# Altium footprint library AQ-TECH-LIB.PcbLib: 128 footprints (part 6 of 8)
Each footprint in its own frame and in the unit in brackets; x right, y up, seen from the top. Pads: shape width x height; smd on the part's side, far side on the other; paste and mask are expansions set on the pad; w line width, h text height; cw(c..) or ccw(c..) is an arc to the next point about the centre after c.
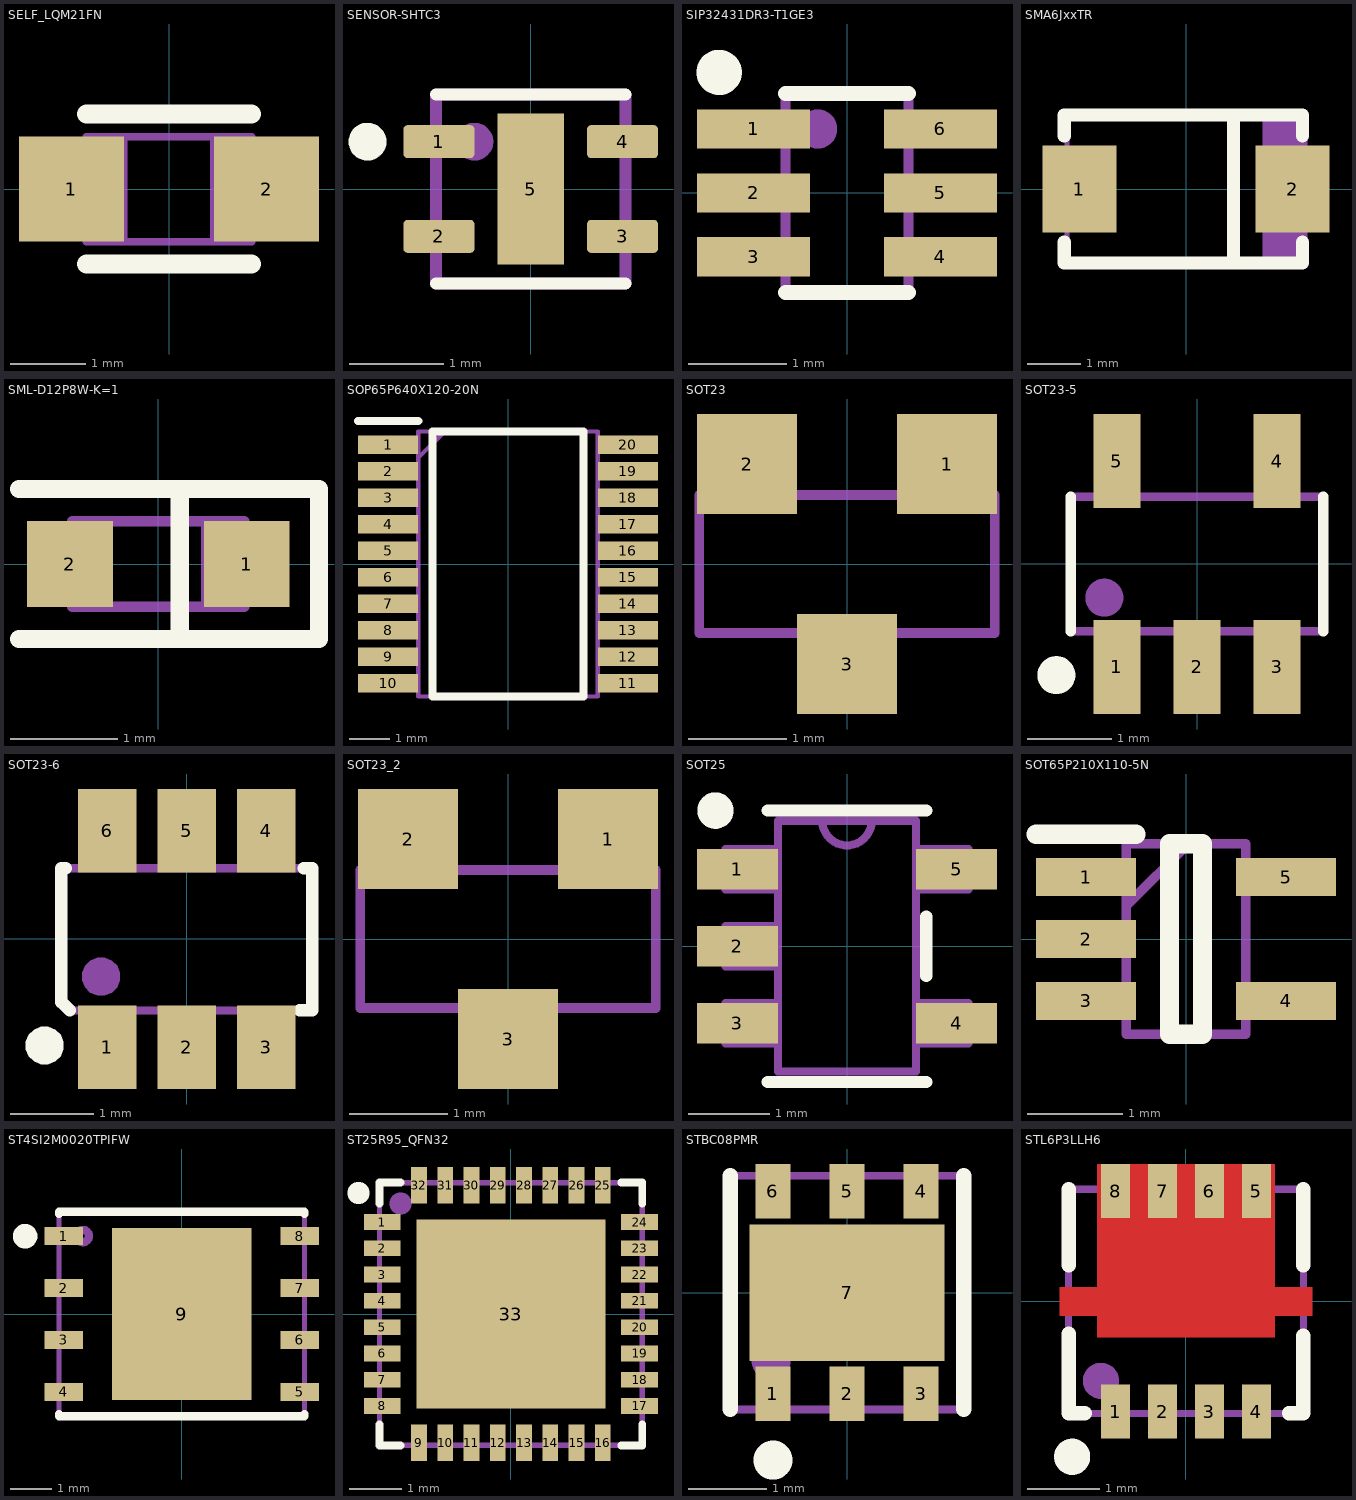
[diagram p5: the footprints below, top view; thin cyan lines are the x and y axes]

## SELF_LQM21FN [mm]
height 1.45
pads (2):
  rect 1.4x1.4 smd paste+0 mask+0.1: 1(-1.3,0) 2(1.3,0)
Top Overlay:
  lines w0.25: -1.1,-1 1.1,-1 ; -1.1,1 1.1,1
Mechanical 3:
  lines w0.1: -1.1,-0.7 -1.1,0.7 ; -1.1,-0.7 -0.6,-0.7 -0.6,0.7 -1.1,0.7 ; -1.1,-0.7 -1.1,0.7 ; -1.1,-0.7 1.1,-0.7 ; -1.1,0.7 1.1,0.7 ; 1.1,-0.7 1.1,0.7 ; 1.1,-0.7 0.6,-0.7 0.6,0.7 1.1,0.7 ; 1.1,-0.7 1.1,0.7
  text ".Designator" at -0.725,-0.125 h0.84
3D body: height 1.45, standoff 0, extent -1.1,-0.7 1.1,0.7

## SENSOR-SHTC3 [mm]
height 0.75
pads (5):
  rrect25% 0.75x0.35 smd mask+0.05: 1(-0.97,0.5) 2(-0.97,-0.5) 3(0.97,-0.5) 4(0.97,0.5)
  rect 0.7x1.6 smd mask+0.05: 5(0,0)
Top Overlay:
  circle w0.2: c-1.725,0.5 r0.1
  lines w0.127: -1,-1 1,-1 ; -1,1 1,1
Mechanical 3:
  circle w0.2: c-0.595,0.5 r0.1
  lines w0.127: -1,-1 -1,1 1,1 1,-1 -1,-1
  text ".Designator" at 0,0 h0.84
3D body "step_temp.STEP": height 0.75, standoff 0, extent -1,-1 1,1

## SIP32431DR3-T1GE3 [mm] "SC70-6"
height 1.1
pads (6):
  rect 1.15x0.4 smd mask+0.05: 1(-0.95,0.65) 2(-0.95,0) 3(-0.95,-0.65) 4(0.95,-0.65) 5(0.95,0) 6(0.95,0.65)
Top Overlay:
  circle w0.3: c-1.3,1.225 r0.08
  lines w0.15: -0.625,-1.012 0.625,-1.012 ; -0.625,1.012 0.625,1.012
Mechanical 3:
  circle w0.2: c-0.3,0.65 r0.1
  lines w0.1: -0.625,-1.012 -0.625,1.012 0.625,1.012 0.625,-1.012 -0.625,-1.012
  text ".Designator" at 0,0 h0.84
3D body "MIC94092YC6_TR.stp": height 1.1, standoff 0, extent -1.05,-1.012 1.05,1.012

## SMA6JxxTR [mm]
height 2.65
pads (2):
  rect 1.4x1.64 smd paste+0 mask+0.1: 1(-2.015,0) 2(2.015,0)
Top Overlay:
  lines w0.25: -2.3,-1 -2.3,-1.4 2.2,-1.4 2.2,-1 ; -2.3,1 -2.3,1.4 2.2,1.4 2.2,1 ; 0.9,-1.3 0.9,1.4
Mechanical 3:
  region: 1.5,-1.39 2.24,-1.39 2.24,1.4 1.5,1.4
  lines w0.1: 1.5,-1.395 1.5,1.395 ; -2.64,-0.735 -2.64,0.735 -2.25,0.735 -2.25,-0.735 -2.64,-0.735 ; -2.25,-1.395 -2.25,1.395 2.25,1.395 2.25,-1.395 -2.25,-1.395 ; 2.25,-0.735 2.64,-0.735 2.64,0.735 2.25,0.735 2.25,-0.735
  text ".Designator" at 0,0 h0.84
3D body "DO214AC(refusion).stp": height 2.4, standoff 0, extent -2.6,-1.3 2.6,1.3

## SML-D12P8W-K=1 [mm] "LED VERTE"
height 0.55
pads (2):
  rect 0.8x0.8 smd: 1(0.825,0) 2(-0.825,0)
Top Overlay:
  lines w0.17: -1.3,-0.7 1.5,-0.7 1.5,0.7 1.05,0.7 -1.3,0.7 ; 0.2,-0.7 0.2,0.7
Mechanical 3:
  rectangle: 0.4,-0.4 0.8,0.4
  lines w0.1: -0.8,-0.4 -0.8,0.4 0.8,0.4 0.8,-0.4 -0.8,-0.4
  text "'.Designator'" at -1.75,-0.65 h0.8
3D body: height 0.55, standoff 0, extent -0.8,-0.4 0.8,0.4

## SOP65P640X120-20N [mm]
pads (20):
  rect 1.475x0.45 smd mask+0.05: 1(-2.938,2.925) 2(-2.938,2.275) 3(-2.938,1.625) 4(-2.938,0.975) 5(-2.938,0.325) 6(-2.938,-0.325) 7(-2.938,-0.975) 8(-2.938,-1.625) 9(-2.938,-2.275) 10(-2.938,-2.925) 11(2.938,-2.925) 12(2.938,-2.275) 13(2.938,-1.625) 14(2.938,-0.975) 15(2.938,-0.325) 16(2.938,0.325) 17(2.938,0.975) 18(2.938,1.625) 19(2.938,2.275) 20(2.938,2.925)
Top Overlay:
  lines w0.2: -3.675,3.5 -2.2,3.5 ; -1.85,-3.25 -1.85,3.25 1.85,3.25 1.85,-3.25 -1.85,-3.25
Mechanical 3:
  lines w0.1: -2.2,2.6 -1.55,3.25 ; -2.2,-3.25 2.2,-3.25 2.2,3.25 -2.2,3.25 -2.2,-3.25
  text "'.Designator'" at -0.025,0 h0.8
3D body "STM32L010F4P6.stp": height 1.2, standoff 0, extent -3.2,-3.25 3.2,3.25

## SOT23 [mil]
height 44.09
pads (3):
  rect 40x40 smd: 1(40,40) 2(-40,40) 3(0,-40)
Mechanical 3:
  lines w3.94: -59.1,-27.6 -59.1,27.6 -47,27.6 -47,49.2 -28,49.2 -28,27.6 28,27.6 28,49.2 47,49.2 47,27.6 59.1,27.6 59.1,-27.6 9.5,-27.6 9.5,-49.2 -9.5,-49.2 -9.5,-27.6 -59.1,-27.6
  text ".Designator" at -28,-21.65 h33.07
3D body "Conception1.stp": height 43.31, standoff 0, extent -59.05,-49.21 59.06,49.22

## SOT23-5 [mil] "refusion"
height 57.09
pads (5):
  rect 22x44 smd paste+0 mask+3.94: 1(-37.4,-48.11) 2(0,-48.11) 3(37.4,-48.11) 4(37.4,48.11) 5(-37.4,48.11)
Top Overlay:
  lines w4.92: -59.06,-31.5 -59.06,31.5 ; 59.06,-31.5 59.06,31.5
  lines w9.84: -65.75,-55.91 cw(c-65.75,-51.97) -65.75,-48.03 cw(c-65.75,-51.97) -65.75,-55.91
Mechanical 3:
  lines w3.94: -59.06,-31.5 59.06,-31.5 59.06,31.5 -59.06,31.5 -59.06,-31.5
  lines w9.84: -43.31,-19.68 ccw(c-43.31,-15.75) -43.31,-11.81 ccw(c-43.31,-15.75) -43.31,-19.68
  text ".Designator" at -54.08,-9.65 h33.07
3D body "sot23-5.stp": height 43.31, standoff 0, extent -59.05,-49.2 59.06,49.22

## SOT23-6 [mm] "refusion"
height 1.4
pads (6):
  rect 0.7x1 smd paste+0 mask+0.05: 1(-0.95,-1.295) 2(0,-1.295) 3(0.95,-1.295) 4(0.95,1.295) 5(0,1.295) 6(-0.95,1.295)
Top Overlay:
  region: -1.7,-1.5 -1.745,-1.5 -1.827,-1.466 -1.891,-1.402 -1.925,-1.32 -1.925,-1.23 -1.891,-1.148 -1.827,-1.084 -1.745,-1.05 -1.7,-1.05 -1.655,-1.05 -1.573,-1.084 -1.509,-1.148 -1.475,-1.23 -1.475,-1.32 -1.509,-1.402 -1.573,-1.466 -1.655,-1.5
  lines w0.15: -1.45,0.845 -1.5,0.845 -1.5,-0.755 -1.4,-0.855 ; 1.35,-0.855 1.5,-0.855 1.5,0.845 1.4,0.845
Mechanical 3:
  region: -1.025,-0.675 -1.07,-0.675 -1.152,-0.641 -1.216,-0.577 -1.25,-0.495 -1.25,-0.405 -1.216,-0.323 -1.152,-0.259 -1.07,-0.225 -1.025,-0.225 -0.98,-0.225 -0.898,-0.259 -0.834,-0.323 -0.8,-0.405 -0.8,-0.495 -0.834,-0.577 -0.898,-0.641 -0.98,-0.675
  lines w0.1: -1.5,-0.755 -1.5,0.845 1.5,0.845 1.5,-0.855 -1.4,-0.855 -1.5,-0.755
  text ".Designator" at 0,0 h1
3D body "SOT23-6(refusion).stp": height 1.45, standoff 0, extent -1.5,-1.5 1.5,1.5

## SOT23_2 [mil]
pads (3):
  rect 40x40 smd: 1(40,40) 2(-40,40) 3(0,-40)
Mechanical 3:
  lines w3.94: -59.1,-27.6 -9.5,-27.6 -9.5,-49.2 9.5,-49.2 9.5,-27.6 59.1,-27.6 59.1,27.6 47,27.6 47,49.2 28,49.2 28,27.6 -28,27.6 -28,49.2 -47,49.2 -47,27.6 -59.1,27.6 -59.1,-27.6
  text ".Designator" at -28,-21.65 h33.07
3D body "Conception1.stp": height 43.31, standoff 0, extent -59.05,-49.21 59.06,49.22

## SOT25 [mm]
height 1.4
pads (5):
  rect 1x0.5 smd: 1(-1.353,0.95) 2(-1.353,0) 3(-1.353,-0.95) 4(1.353,-0.95) 5(1.353,0.95)
Top Overlay:
  circle w0.25: c-1.625,1.675 r0.1
  lines w0.152: -0.977,-1.677 0.977,-1.677 ; -0.977,1.677 0.977,1.677 ; 0.977,-0.367 0.977,0.367
Mechanical 3:
  lines w0.1: -0.305,1.55 ccw(c0,1.55) 0.305,1.55 ; -1.5,-1.2 -0.85,-1.2 -0.85,-0.7 -1.5,-0.7 -1.5,-1.2 ; -1.5,-0.25 -0.85,-0.25 -0.85,0.25 -1.5,0.25 -1.5,-0.25 ; -1.5,0.7 -0.85,0.7 -0.85,1.2 -1.5,1.2 -1.5,0.7 ; -0.85,-1.55 -0.85,1.55 0.85,1.55 0.85,-1.55 -0.85,-1.55 ; 0.85,-1.2 1.5,-1.2 1.5,-0.7 0.85,-0.7 0.85,-1.2 ; 0.85,0.7 1.5,0.7 1.5,1.2 0.85,1.2 0.85,0.7
  text ".Designator" at 0.4,-1.125 h0.84
3D body "SOT25_DIO.step": height 1.45, standoff 0, extent -1.5,-1.55 1.5,1.55

## SOT65P210X110-5N [mm]
pads (5):
  rect 1.05x0.4 smd mask+0.05: 1(-1.05,0.65) 2(-1.05,0) 3(-1.05,-0.65) 4(1.05,-0.65) 5(1.05,0.65)
Top Overlay:
  lines w0.2: -1.575,1.1 -0.525,1.1 ; -0.175,-1 -0.175,1 0.175,1 0.175,-1 -0.175,-1
Mechanical 3:
  lines w0.1: -0.625,0.35 0.025,1 ; -0.625,-1 0.625,-1 0.625,1 -0.625,1 -0.625,-1
  text ".Designator" at 0.245,-1.374 h0.84
3D body "MIC5253-1.8YC5-TR.stp": height 1.1, standoff 0, extent -1.05,-1 1.05,1

## ST4SI2M0020TPIFW [mm]
height 1
pads (9):
  rect 0.94x0.44 smd mask+0.05: 1(-2.885,1.905) 2(-2.885,0.635) 3(-2.885,-0.635) 4(-2.885,-1.905) 5(2.885,-1.905) 6(2.885,-0.635) 7(2.885,0.635) 8(2.885,1.905)
  rect 3.4x4.2 smd paste-3 mask+0.05: 9(0,0)
Top Overlay:
  circle w0.3: c-3.825,1.9 r0.15
  lines w0.2: -3,-2.445 -3,-2.5 3,-2.5 3,-2.445 ; -3,2.445 -3,2.5 3,2.5 3,2.445
Top Paste:
  region: -0.23,0.23 -1.24,0.23 -1.24,1.64 -0.23,1.64
  region: -0.23,-1.64 -1.24,-1.64 -1.24,-0.23 -0.23,-0.23
  region: 1.24,0.23 0.23,0.23 0.23,1.64 1.24,1.64
  region: 1.24,-1.64 0.23,-1.64 0.23,-0.23 1.24,-0.23
Mechanical 3:
  circle w0.2: c-2.415,1.905 r0.15
  lines w0.127: -3,-2.5 -3,2.5 3,2.5 3,-2.5 -3,-2.5
3D body: height 1, standoff 0, extent -3,-2.5 3,2.5
3D body: height 1.01, standoff 0, extent -2.665,1.655 -2.165,2.155

## ST25R95_QFN32 [mm]
height 1
pads (33):
  rect 0.7x0.3 smd mask+0.05: 1(-2.45,1.75) 2(-2.45,1.25) 3(-2.45,0.75) 4(-2.45,0.25) 5(-2.45,-0.25) 6(-2.45,-0.75) 7(-2.45,-1.25) 8(-2.45,-1.75) 17(2.45,-1.75) 18(2.45,-1.25) 19(2.45,-0.75) 20(2.45,-0.25) 21(2.45,0.25) 22(2.45,0.75) 23(2.45,1.25) 24(2.45,1.75)
  rect 0.3x0.7 smd mask+0.05: 9(-1.75,-2.45) 10(-1.25,-2.45) 11(-0.75,-2.45) 12(-0.25,-2.45) 13(0.25,-2.45) 14(0.75,-2.45) 15(1.25,-2.45) 16(1.75,-2.45) 25(1.75,2.45) 26(1.25,2.45) 27(0.75,2.45) 28(0.25,2.45) 29(-0.25,2.45) 30(-0.75,2.45) 31(-1.25,2.45) 32(-1.75,2.45)
  rect 3.6x3.6 smd mask+0.05: 33(0,0)
Top Overlay:
  circle w0.4: c-2.9,2.3 r0.01
  lines w0.15: -2.5,-2.1 -2.5,-2.5 -2.1,-2.5 ; -2.5,2.1 -2.5,2.5 -2.1,2.5 ; 2.1,-2.5 2.5,-2.5 2.5,-2.1 ; 2.1,2.5 2.5,2.5 2.5,2.1
Mechanical 3:
  circle w0.4: c-2.1,2.1 r0.01
  lines w0.1: -2.5,-2.5 -2.5,2.5 2.5,2.5 2.5,-2.5 -2.5,-2.5
  text ".Designator" at 0.95,0.5 h0.84
3D body: height 1, standoff 0, extent -2.5,-2.5 2.5,2.5

## STBC08PMR [mm] "DFN6 3.0X3.0MM PAS 0.95MM"
height 1
pads (7):
  rect 0.45x0.7 smd mask+0.05: 1(-0.95,-1.3) 2(0,-1.3) 3(0.95,-1.3) 4(0.95,1.3) 5(0,1.3) 6(-0.95,1.3)
  rect 2.5x1.75 smd mask+0.025: 7(0,0)
Top Overlay:
  circle w0.4: c-0.95,-2.15 r0.05
  lines w0.2: -1.5,-1.5 -1.5,1.5 ; 1.5,-1.5 1.5,1.5
Mechanical 3:
  circle w0.4: c-0.973,-0.875 r0.05
  lines w0.1: -1.5,-1.5 -1.5,1.5 1.5,1.5 1.5,-1.5 -1.5,-1.5
  text ".Designator" at -0.8,0 h0.84
3D body: height 1, standoff 0, extent -1.5,-1.5 1.5,1.5
3D body: height 1.01, standoff 0, extent -1.221,-1.124 -0.723,-0.625

## STL6P3LLH6 [mm] "POWER FLAT 3.3X3.3 Type F"
height 0.9
pads (8):
  rect 0.4x0.75 smd paste+0 mask+0.05: 1(-0.975,-1.525) 2(-0.325,-1.525) 3(0.325,-1.525) 4(0.975,-1.525) 5(0.975,1.525) 6(0.325,1.525) 7(-0.325,1.525) 8(-0.975,1.525)
Top Layer:
  rectangle: -1.75,-0.2 1.75,0.2
  region: -1.225,-0.5 1.225,-0.5 1.225,1.9 -1.225,1.9
Top Overlay:
  circle w0.3: c-1.575,-2.15 r0.1
  lines w0.2: -1.625,-0.45 -1.625,-1.55 -1.4,-1.55 ; -1.625,0.5 -1.625,1.55 ; 1.425,-1.55 1.625,-1.55 1.625,-0.475 ; 1.625,0.5 1.625,1.55
Mechanical 3:
  circle w0.3: c-1.175,-1.1 r0.1
  lines w0.1: -1.625,-1.55 -1.625,1.55 1.625,1.55 1.625,-1.55 -1.625,-1.55
  text ".Designator" at -0.04,-0.04 h0.84
3D body: height 1, standoff 0, extent -1.625,-1.55 1.625,1.55
3D body: height 1.01, standoff 0, extent -1.424,-1.35 -0.926,-0.851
